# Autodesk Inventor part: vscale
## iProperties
Created: 2007-02
Part Number: vscale
Document SubType Name: Modeling
Designer: John Blackburn
Material: Steel, Mild
Author: John Blackburn
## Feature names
1. Extrusion1
2. Fillet1
